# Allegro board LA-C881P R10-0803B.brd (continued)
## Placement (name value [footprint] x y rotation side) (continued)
PC311  0.1U_0402_25V6  [C_0402]  43.71 25.74 0 bottom
PC312  1U_0603_10V6K  [C_0603]  45.95 31.07 0 bottom
PC313  1U_0805_25V6K  [C_0805]  47.44 27.01 180 bottom
PC314  10U_0805_25V6K  [C_0805]  72.78 38.31 0 top
PC315  10U_0805_25V6K  [C_0805]  72.78 36.53 0 bottom
PC316  0.1U_0603_25V7K  [C_0603]  73.06 35.01 0 bottom
PC317  10U_0805_25V6K  [C_0805]  72.78 38.31 0 bottom
PC318  0.1U_0402_25V6  [C_0402]  40.36 24.27 90 bottom
PC319  0.1U_0603_25V7K  [C_0603]  71.86 43.07 90 top
PC320  0.1U_0603_25V7K  [C_0603]  73.06 35.01 0 top
PC321  10U_0805_25V6K  [C_0805]  72.78 36.53 0 top
PC322  0.047U_0603_25V7M  [C_0603]  47.35 28.53 180 bottom
PC323  0.1U_0603_25V7K  [C_0603]  73.89 31.33 270 top
PC324  10U_0805_25V6K  [C_0805]  68.58 31.49 270 bottom
PC325  10U_0805_25V6K  [C_0805]  72.28 31.5 270 bottom
PC326  10U_0805_25V6K  [C_0805]  70.48 31.5 270 bottom
PC327  10U_0805_25V6K  [C_0805]  68.6 31.47 270 top
PC328  10U_0805_25V6K  [C_0805]  70.5 31.45 270 top
PC329  10U_0805_25V6K  [C_0805]  72.29 31.45 270 top
PC330  100P_0402_50V8J  [C_0402]  39.47 25.18 270 bottom
PC331  100P_0402_50V8J  [C_0402]  39.47 25.18 270 top
PC332  100P_0402_50V8J  [C_0402]  39.27 28.91 0 top
PC333  1000P_0603_50V7K  [C_0603]  52.81 36.41 180 bottom
PC334  0.1U_0402_25V6  [C_0402]  44.3 34.13 270 bottom
PC335  0.1U_0402_25V6  [C_0402]  43.42 33.49 180 bottom
PC336  0.1U_0402_25V6  [C_0402]  42.51 34.38 0 bottom
PC337  1U_0603_25V6K  [C_0603]  40.49 33.11 90 bottom
PC400  100P_0402_50V8J  [C_0402]  162.92 64.3 270 bottom
PC401  0.01UF_0402_25V7K  [C_0402]  163.81 64.3 270 bottom
PC402  .1U_0402_16V7K  [C_0402]  173.41 58.63 180 bottom
PC403  1000P_0402_50V7K  [C_0402]  165.58 64.3 270 bottom
PC404  0.47U_0603_16V7K  [C_0603]  171.74 55.71 0 top
PC405  .1U_0402_16V7K  [C_0402]  175.36 58.38 270 top
PC406  0.1U_0402_25V6  [C_0402]  167.03 60.03 0 top
PC407  1U_0603_10V6K  [C_0603]  164.38 58.44 0 top
PC500  0.1U_0402_25V6  [C_0402]  89.76 22.44 270 top
PC501  2200P_0402_50V7K  [C_0402]  90.65 22.44 270 top
PC502  10U_0805_25V6K  [C_0805]  93.07 22.56 270 bottom
PC503  10U_0805_25V6K  [C_0805]  93.07 22.56 270 top
PC504  0.1U_0603_25V7K  [C_0603]  86.34 22.5 270 top
PC505  22U_0603_6.3V6M  [C_0603]  78.93 22.67 180 bottom
PC506  22U_0603_6.3V6M  [C_0603]  78.91 21.42 180 bottom
PC507  22U_0603_6.3V6M  [C_0603]  78.91 22.18 180 top
PC508  22U_0603_6.3V6M  [C_0603]  78.91 20.15 180 bottom
PC509  4.7U_0603_6.3V6M  [C_0603]  86.53 17.23 180 bottom
PC510  680P_0603_50V7K  [C_0603]  86.27 23.83 0 top
PC511  1000P_0402_25V8J  [C_0402]  90.15 17.94 270 bottom
PC512  0.1U_0603_25V7K  [C_0603]  59.98 44.03 180 top
PC513  0.1U_0402_25V6  [C_0402]  64.24 44.23 270 top
PC514  2200P_0402_50V7K  [C_0402]  63.35 44.23 270 top
PC515  10U_0805_25V6K  [C_0805]  66.78 44.37 270 bottom
PC516  10U_0805_25V6K  [C_0805]  68.56 44.37 270 bottom
PC517  4.7U_0603_6.3V6M  [C_0603]  61.25 38.31 180 top
PC518  22U_0603_6.3V6M  [C_0603]  55.92 49.11 180 bottom
PC519  22U_0603_6.3V6M  [C_0603]  55.95 46.63 180 bottom
PC520  22U_0603_6.3V6M  [C_0603]  55.92 47.84 180 bottom
PC521  22U_0603_6.3V6M  [C_0603]  53.91 46.63 180 top
PC522  22U_0603_6.3V6M  [C_0603]  53.89 49.11 180 top
PC523  4.7U_0603_6.3V6M  [C_0603]  61.25 37.93 180 bottom
PC524  680P_0603_50V7K  [C_0603]  60.74 39.84 0 top
PC525  1000P_0402_25V8J  [C_0402]  63.6 39.28 270 bottom
PC526  22U_0603_6.3V6M  [C_0603]  78.91 20.91 180 top
PC527  22U_0603_6.3V6M  [C_0603]  53.89 47.84 180 top
PC528  10U_0805_25V6K  [C_0805]  66.78 44.37 270 top
PC529  10U_0805_25V6K  [C_0805]  68.56 44.37 270 top
PC600  10U_0603_25V6M  [C_0603]  169.08 34.38 180 top
PC601  10U_0603_25V6M  [C_0603]  169.08 35.65 180 top
PC602  0.1U_0402_25V6  [C_0402]  168.96 36.79 180 top
PC603  2200P_0402_25V7K  [C_0402]  169.95 35.14 0 top
PC604  680P_0402_50V7K  [C_0402]  172.82 23.66 270 top
PC605  .1U_0402_16V7K  [C_0402]  172.95 27.97 270 top
PC606  1U_0402_6.3V6K  [C_0402]  172.49 28.91 0 top
PC607  2.2U_0402_6.3V6M  [C_0402]  172.49 29.8 0 top
PC608  22U_0603_6.3V6M  [C_0603]  166.09 26.95 270 top
PC609  330P_0402_50V7K  [C_0402]  173.41 30.69 180 top
PC610  22U_0603_6.3V6M  [C_0603]  164.78 23.29 90 top
PC611  22U_0603_6.3V6M  [C_0603]  164.82 19.96 270 top
PC612  22U_0603_6.3V6M  [C_0603]  167.36 19.96 270 top
PC613  22U_0603_6.3V6M  [C_0603]  166.09 19.96 270 top
PC614  1U_0402_10V6K  [C_0402]  166.55 31.96 180 top
PC615  22U_0603_6.3V6M  [C_0603]  166.66 29.55 180 top
PC616  22U_0603_6.3V6M  [C_0603]  166.66 30.82 180 top
PC617  0.1U_0402_10V7K  [C_0402]  164.95 32.98 90 top
PC618  0.1U_0402_10V7K  [C_0402]  163.93 29.42 180 top
PC700  0.22U_0402_10V6K  [C_0402]  203.1 61.43 0 bottom
PC701  680P_0402_50V7K  [C_0402]  201.88 57.57 270 bottom
PC702  2200P_0402_50V7K  [C_0402]  195.3 63.03 270 top
PC703  0.1U_0603_25V7K  [C_0603]  199.49 61.49 270 top
PC704  0.1U_0402_25V6  [C_0402]  195.3 63.03 270 bottom
PC705  10U_0805_25V6K  [C_0805]  196.7 63.8 270 top
PC706  10U_0805_25V6K  [C_0805]  196.7 63.8 270 bottom
PC707  22P_0402_50V8J  [C_0402]  204.01 64.09 180 bottom
PC708  22U_0805_6.3VAM  [C_0805]  194.79 55.67 270 top
PC709  22U_0805_6.3VAM  [C_0805]  194.79 57.4 90 top
PC710  22U_0805_6.3VAM  [C_0805]  194.77 55.67 270 bottom
PC711  22U_0805_6.3VAM  [C_0805]  194.74 57.4 90 bottom
PC712  4.7U_0603_6.3V6K  [C_0603]  202.92 65.68 90 bottom
PC713  4.7U_0603_6.3V6K  [C_0603]  200.44 66.25 0 bottom
PC800  0.1U_0402_25V6  [C_0402]  173.97 78.06 90 top
PC801  22P_0402_50V8J  [C_0402]  170.66 70.82 90 top
PC802  22U_0805_6.3VAM  [C_0805]  168.12 73.36 0 top
PC803  0.1U_0402_25V6  [C_0402]  176.63 76.16 0 top
PC804  2200P_0402_50V7K  [C_0402]  176.63 75.27 0 top
PC805  10U_0805_25V6K  [C_0805]  176.76 77.56 0 top
PC806  3300P_0402_50V7-K  [C_0402]  176.63 74.25 0 top
PC807  680P_0402_50V7K  [C_0402]  170.54 79.84 180 top
PC900  0.1U_0402_25V6  [C_0402]  171.43 43.39 90 top
PC901  22P_0402_50V8J  [C_0402]  166.73 38.19 90 top
PC902  22U_0805_6.3VAM  [C_0805]  161.99 44.03 180 top
PC903  0.1U_0402_25V6  [C_0402]  171.43 41.61 90 top
PC904  2200P_0402_50V7K  [C_0402]  172.31 41.61 90 top
PC905  10U_0805_25V6K  [C_0805]  171.81 40.47 270 top
PC906  3300P_0402_50V7-K  [C_0402]  170.28 38.9 270 top
PC907  680P_0402_50V7K  [C_0402]  163.6 40.45 270 top
PC1004  0.1U_0402_25V6  [C_0402]  64.49 51.9 270 bottom
PC1005  0.22U_0603_25V7K  [C_0603]  64.62 55.71 90 bottom
PC1006  47P_0402_50V8J~D  [C_0402]  62.33 51.01 180 top
PC1007  1U_0603_10V6K  [C_0603]  65.51 53.3 0 bottom
PC1014  220P_0402_50V7K  [C_0402]  69.7 46.82 270 top
PC1019  0.01U_0402_50V7K  [C_0402]  67.79 46.44 90 bottom
PC1020  2200P_0402_50V7K  [C_0402]  65.89 46.06 90 top
PC1021  68P_0402_50V8J  [C_0402]  66.9 48.09 90 top
PC1022  0.082U_0402_16V7K  [C_0402]  68.68 48.22 180 bottom
PC1056  68P_0402_50V8J  [C_0402]  70.97 53.17 0 bottom
PC1064  2200P_0402_50V7K  [C_0402]  71.48 55.84 270 bottom
PC1065  330P_0402_50V7K  [C_0402]  70.97 52.28 0 bottom
PC1066  10U_0805_25V6K  [C_0805]  66.65 62.16 90 top
PC1067  0.033U_0402_16V7K  [C_0402]  73.64 56.9 0 bottom
PC1068  2200P_0402_25V7K  [C_0402]  67.54 58.17 90 top
PC1069  2200P_0402_50V7K  [C_0402]  73.89 56.73 90 top
PC1070  0.022U_0402_16V7K  [C_0402]  70.59 48.22 90 top
PC1071  0.047U_0402_25V7K  [C_0402]  67.54 58.17 90 bottom
PC1072  2200P_0402_25V7K  [C_0402]  69.52 59.39 180 top
PC1073  100U_D_20VM_R55M  [C_D]  77.19 43.01 0 bottom
PC1074  0.01U_0402_50V7K  [C_0402]  70.59 58.25 0 bottom
PC1075  0.047U_0402_25V7K  [C_0402]  73.64 56.02 0 bottom
PC1076  2200P_0402_50V7K  [C_0402]  69.06 62.49 90 top
PC1077  0.082U_0402_16V7K  [C_0402]  69.57 58.25 180 bottom
PC1078  0.1U_0402_25V6  [C_0402]  66.65 58.17 90 bottom
PC1079  0.1U_0402_25V6K~D  [C_0402]  68.17 62.49 90 top
PC1080  330P_0402_50V7K  [C_0402]  69.57 56.22 270 bottom
PC1081  10P_0402_50V8J  [C_0402]  68.68 56.22 270 bottom
PC1082  0.22U_0603_16V7K  [C_0603]  61.57 61.87 270 top
PC1083  .1U_0402_16V7K  [C_0402]  75.54 56.85 270 bottom
PC1084  .1U_0402_16V7K  [C_0402]  72.37 48.22 90 top
PC1085  0.033U_0402_16V7K  [C_0402]  69.7 48.22 0 bottom
PC1086  680P_0603_50V7K  [C_0603]  69.32 67.27 180 bottom
PC1087  .1U_0402_16V7K  [C_0402]  66.65 60.03 0 bottom
PC1088  2200P_0402_50V7K  [C_0402]  72.37 50 180 bottom
PC1089  2200P_0402_25V7K  [C_0402]  66.9 55.33 0 bottom
PC1090  1500P_0402_50V7K  [C_0402]  74.91 54.06 0 top
PC1091  330P_0402_50V7K  [C_0402]  68.61 59.39 0 bottom
PC1092  0.082U_0402_16V7K  [C_0402]  73.89 54.95 90 top
PC1093  10U_0805_25V6K  [C_0805]  66.65 62.44 90 bottom
PC1094  0.1U_0402_25V6  [C_0402]  69.7 49.11 0 bottom
PC1095  680P_0402_50V7K  [C_0402]  66.9 46.95 270 top
PC1096  680P_0402_50V7K  [C_0402]  77.06 51.39 180 top
PC1097  1U_0402_10V6K  [C_0402]  64.16 65.24 0 top
PC1098  330P_0402_50V7K  [C_0402]  68.68 46.44 90 bottom
PC1099  0.01U_0402_50V7K  [C_0402]  75.79 55.84 180 top
PC1100  10U_0805_25V6K  [C_0805]  80.79 58.89 0 top
PC1101  10U_0805_25V6K  [C_0805]  80.79 60.66 0 bottom
PC1102  10U_0805_25V6K  [C_0805]  80.79 60.66 0 top
PC1103  0.1U_0402_25V6K~D  [C_0402]  78.92 59.65 180 top
PC1104  2200P_0402_50V7K  [C_0402]  80.42 62.06 0 top
PC1105  10U_0805_25V6K  [C_0805]  80.79 58.89 0 bottom
PC1106  0.22U_0603_16V7K  [C_0603]  84.62 67.9 180 top
PC1107  10U_0805_25V6K  [C_0805]  80.49 52.16 0 bottom
PC1108  10U_0805_25V6K  [C_0805]  80.49 52.16 0 top
PC1109  10U_0805_25V6K  [C_0805]  78.97 53.64 270 bottom
PC1110  1000P_0402_50V7K  [C_0402]  80.42 63.84 0 top
PC1111  2200P_0402_50V7K  [C_0402]  80.42 54.44 0 top
PC1112  0.1U_0402_25V6K~D  [C_0402]  80.42 53.55 0 top
PC1113  10P_0402_50V8J  [C_0402]  80.42 62.95 0 top
PC1114  1U_0402_10V6K  [C_0402]  84.94 67.01 90 bottom
PC1115  47P_0603_50V8J  [C_0603]  85.38 61.05 180 top
PC1116  0.22U_0603_16V7K  [C_0603]  77.64 57.62 0 top
PC1117  10P_0402_50V8J  [C_0402]  80.42 56.22 0 top
PC1118  1000P_0402_50V7K  [C_0402]  80.42 55.33 0 top
PC1119  1U_0402_10V6K  [C_0402]  85.5 58.38 0 bottom
PC1120  10U_0805_25V6K  [C_0805]  78.97 40.73 0 top
PC1121  10U_0805_25V6K  [C_0805]  78.97 44.28 0 top
PC1122  10U_0805_25V6K  [C_0805]  78.97 42.5 0 top
PC1123  0.1U_0402_25V6K~D  [C_0402]  80.29 45.68 0 top
PC1124  2200P_0402_50V7K  [C_0402]  80.29 46.57 0 top
PC1125  47P_0603_50V8J  [C_0603]  85.26 53.68 180 top
PC1126  0.22U_0603_16V7K  [C_0603]  77.38 50.12 0 top
PC1127  10P_0402_50V8J  [C_0402]  80.29 47.46 0 top
PC1128  1000P_0402_50V7K  [C_0402]  80.29 48.35 0 top
PC1129  1U_0402_10V6K  [C_0402]  85.5 50.76 0 bottom
PC1130  47P_0603_50V8J  [C_0603]  85.51 46.06 180 top
PC1131  330P_0402_50V8J  [C_0402]  67.67 51.65 270 bottom
PC1132  330P_0402_50V7K  [C_0402]  75.79 54.95 180 top
PC1133  0.022U_0402_16V7K  [C_0402]  71.48 48.22 90 top
PC1134  680P_0402_50V7K  [C_0402]  71.55 60.03 180 top
PC1135  100U_D_20VM_R55M  [C_D]  77.19 38.31 0 bottom
PC1200  22U_0603_6.3V6M  [C_0603]  128.94 62.06 0 top
PC1201  22U_0603_6.3V6M  [C_0603]  132.88 62.06 180 top
PC1202  22U_0603_6.3V6M  [C_0603]  129.01 59.46 90 top
PC1203  22U_0603_6.3V6M  [C_0603]  130.28 59.46 90 top
PC1204  22U_0603_6.3V6M  [C_0603]  131.55 59.46 90 top
PC1205  22U_0603_6.3V6M  [C_0603]  132.82 59.46 90 top
PC1206  22U_0603_6.3V6M  [C_0603]  132.94 65.17 270 top
PC1207  22U_0603_6.3V6M  [C_0603]  131.67 65.17 270 top
PC1208  22U_0603_6.3V6M  [C_0603]  130.4 65.17 270 top
PC1209  22U_0603_6.3V6M  [C_0603]  129.13 65.17 270 top
PC1210  22U_0603_6.3V6M  [C_0603]  99.52 71.7 90 top
PC1211  22U_0603_6.3V6M  [C_0603]  99.67 66.13 270 top
PC1212  22U_0603_6.3V6M  [C_0603]  94.59 71.71 90 top
PC1213  22U_0603_6.3V6M  [C_0603]  96.94 61.81 0 bottom
PC1214  22U_0603_6.3V6M  [C_0603]  96.94 61.81 0 top
PC1215  22U_0603_6.3V6M  [C_0603]  96.94 63.08 0 top
PC1216  22U_0603_6.3V6M  [C_0603]  95.86 71.71 90 top
PC1217  22U_0603_6.3V6M  [C_0603]  109.83 64.66 90 top
PC1218  22U_0603_6.3V6M  [C_0603]  106.27 61.81 90 top
PC1219  22U_0603_6.3V6M  [C_0603]  126.21 58.12 90 top
PC1220  22U_0603_6.3V6M  [C_0603]  123.67 58.12 90 top
PC1221  22U_0603_6.3V6M  [C_0603]  126.09 65.24 270 top
PC1222  22U_0603_6.3V6M  [C_0603]  124.82 65.24 270 top
PC1223  22U_0603_6.3V6M  [C_0603]  123.55 65.24 270 top
PC1224  22U_0603_6.3V6M  [C_0603]  108.56 64.6 90 top
PC1225  22U_0603_6.3V6M  [C_0603]  111.35 61.81 90 top
PC1226  22U_0603_6.3V6M  [C_0603]  113.26 60.41 270 top
PC1227  22U_0603_6.3V6M  [C_0603]  115.29 64.6 90 top
PC1228  22U_0603_6.3V6M  [C_0603]  110.08 61.81 90 top
PC1229  22U_0603_6.3V6M  [C_0603]  115.29 61.81 90 top
PC1230  22U_0603_6.3V6M  [C_0603]  98.3 71.71 90 top
PC1231  22U_0603_6.3V6M  [C_0603]  96.94 63.08 0 bottom
PC1232  22U_0603_6.3V6M  [C_0603]  107.16 69.49 270 top
PC1233  22U_0603_6.3V6M  [C_0603]  97.08 71.71 90 top
PC1234  22U_0603_6.3V6M  [C_0603]  102.64 69.49 270 bottom
PC1235  22U_0603_6.3V6M  [C_0603]  100.94 66.13 270 top
PC1236  22U_0603_6.3V6M  [C_0603]  98.27 66.13 270 top
PC1237  22U_0603_6.3V6M  [C_0603]  129.9 75.78 180 bottom
PC1238  22U_0603_6.3V6M  [C_0603]  98.4 71.73 90 bottom
PC1239  22U_0603_6.3V6M  [C_0603]  97.13 71.73 90 bottom
PC1240  22U_0603_6.3V6M  [C_0603]  96.88 66.13 270 top
PC1241  22U_0603_6.3V6M  [C_0603]  95.86 71.73 90 bottom
PC1242  22U_0603_6.3V6M  [C_0603]  102.64 69.49 270 top
PC1243  22U_0603_6.3V6M  [C_0603]  104.24 69.49 270 top
PC1244  22U_0603_6.3V6M  [C_0603]  105.89 69.49 270 top
PC1245  22U_0603_6.3V6M  [C_0603]  101.07 69.43 270 top
PC1246  22U_0603_6.3V6M  [C_0603]  107.29 64.54 90 top
PC1247  22U_0603_6.3V6M  [C_0603]  106.02 64.54 90 top
PC1248  22U_0603_6.3V6M  [C_0603]  105.39 58.98 90 top
PC1249  22U_0603_6.3V6M  [C_0603]  99.67 60.28 270 top
PC1250  22U_0603_6.3V6M  [C_0603]  102.21 64.54 90 top
PC1251  22U_0603_6.3V6M  [C_0603]  103.48 64.54 90 top
PC1252  22U_0603_6.3V6M  [C_0603]  104.75 64.54 90 top
PC1253  22U_0603_6.3V6M  [C_0603]  103.99 58.89 90 top
PC1254  22U_0603_6.3V6M  [C_0603]  102.46 58.89 90 top
PC1255  22U_0603_6.3V6M  [C_0603]  101.07 58.89 90 top
PC1256  22U_0603_6.3V6M  [C_0603]  101.07 61.81 90 top
PC1257  22U_0603_6.3V6M  [C_0603]  105 61.81 90 top
PC1258  22U_0603_6.3V6M  [C_0603]  107.54 61.81 90 top
PC1259  1U_0201_6.3V6M  [C_0201]  134.58 66.02 0 top
PC1260  1U_0201_6.3V6M  [C_0201]  127.74 63.46 180 top
PC1261  1U_0201_6.3V6M  [C_0201]  127.74 60.92 180 top
PC1262  1U_0201_6.3V6M  [C_0201]  134.47 60.28 0 top
PC1263  1U_0201_6.3V6M  [C_0201]  134.47 65.36 0 top
PC1264  1U_0201_6.3V6M  [C_0201]  134.47 61.55 0 top
PC1265  1U_0201_6.3V6M  [C_0201]  134.47 62.82 0 top
PC1266  1U_0201_6.3V6M  [C_0201]  127.74 59.65 180 top
PC1267  1U_0201_6.3V6M  [C_0201]  127.74 62.82 180 top
PC1268  1U_0201_6.3V6M  [C_0201]  127.74 64.73 180 top
PC1269  1U_0201_6.3V6M  [C_0201]  127.74 65.36 180 top
PC1270  1U_0201_6.3V6M  [C_0201]  99.54 68.28 0 top
PC1271  1U_0201_6.3V6M  [C_0201]  99.54 67.65 0 top
PC1272  1U_0201_6.3V6M  [C_0201]  127.74 66 180 top
PC1273  1U_0201_6.3V6M  [C_0201]  99.54 68.92 0 top
PC1274  1U_0201_6.3V6M  [C_0201]  94.84 71.84 90 bottom
PC1275  1U_0201_6.3V6M  [C_0201]  128.75 67.78 0 top
PC1276  1U_0201_6.3V6M  [C_0201]  126.21 66.63 0 top
PC1277  1U_0201_6.3V6M  [C_0201]  118.09 65.87 90 top
PC1278  1U_0201_6.3V6M  [C_0201]  120.37 56.85 270 top
PC1279  1U_0201_6.3V6M  [C_0201]  122.53 56.85 270 top
PC1280  1U_0201_6.3V6M  [C_0201]  123.8 56.85 270 top
PC1281  1U_0201_6.3V6M  [C_0201]  126.21 56.85 270 top
PC1282  1U_0201_6.3V6M  [C_0201]  119.1 56.85 270 top
PC1283  1U_0201_6.3V6M  [C_0201]  125.07 56.85 270 top
PC1284  1U_0201_6.3V6M  [C_0201]  126.59 67.52 90 top
PC1285  1U_0201_6.3V6M  [C_0201]  127.36 56.77 270 top
PC1286  1U_0201_6.3V6M  [C_0201]  124.51 66.51 180 top
PC1287  1U_0201_6.3V6M  [C_0201]  119.36 66 90 top
PC1288  1U_0201_6.3V6M  [C_0201]  127.74 61.55 180 top
PC1289  1U_0201_6.3V6M  [C_0201]  94.21 71.84 90 bottom
PC1290  1U_0201_6.3V6M  [C_0201]  99.54 67.01 0 top
PC1291  1U_0201_6.3V6M  [C_0201]  132.36 56.73 0 top
PC1292  1U_0201_6.3V6M  [C_0201]  131.69 56.17 180 top
PC1293  1U_0201_6.3V6M  [C_0201]  127.74 59.01 180 top
PC1294  1U_0201_6.3V6M  [C_0201]  134.47 60.92 0 top
PC1295  1U_0201_6.3V6M  [C_0201]  134.47 62.19 0 top
PC1296  1U_0201_6.3V6M  [C_0201]  134.47 64.73 0 top
PC1297  1U_0201_6.3V6M  [C_0201]  127.74 60.28 180 top
PC1298  1U_0201_6.3V6M  [C_0201]  127.74 62.19 180 top
PC1299  1U_0201_6.3V6M  [C_0201]  127.74 64.09 180 top
PC1300  1U_0201_6.3V6M  [C_0201]  128.07 67.78 180 top
PC1301  1U_0201_6.3V6M  [C_0201]  133.71 55.58 90 top
PC1302  1U_0201_6.3V6M  [C_0201]  134.47 63.46 0 top
PC1303  1U_0201_6.3V6M  [C_0201]  131.67 56.73 180 top
PC1304  1U_0201_6.3V6M  [C_0201]  134.47 64.09 0 top
PC1305  1U_0201_6.3V6M  [C_0201]  132.35 56.17 0 top
PC1306  330_B2_2.5VM_R9M  [C_B2]  97.51 44.89 90 bottom
PC1307  330_B2_2.5VM_R9M  [C_B2]  97.03 47.96 180 bottom
PC1308  330_B2_2.5VM_R9M  [C_B2]  97.03 68.54 180 bottom
PC1309  330_B2_2.5VM_R9M  [C_B2]  97.02 65.33 180 bottom
PC1310  22U_0603_6.3V6M  [C_0603]  135.48 77.17 90 top
PC1311  22U_0603_6.3V6M  [C_0603]  136.25 71.71 0 top
PC1312  22U_0603_6.3V6M  [C_0603]  76.68 67.01 180 bottom
PC1313  22U_0603_6.3V6M  [C_0603]  139.29 77.17 90 top
PC1314  22U_0603_6.3V6M  [C_0603]  135.67 73.36 90 top
PC1315  22U_0603_6.3V6M  [C_0603]  137.14 68.79 90 top
PC1316  22U_0603_6.3V6M  [C_0603]  138.79 64.86 0 top
PC1317  22U_0603_6.3V6M  [C_0603]  138.02 59.9 0 top
PC1318  22U_0603_6.3V6M  [C_0603]  137.64 63.71 180 top
PC1319  22U_0603_6.3V6M  [C_0603]  137.64 66.25 180 top
PC1320  22U_0603_6.3V6M  [C_0603]  137.64 64.98 180 top
PC1321  22U_0603_6.3V6M  [C_0603]  76.68 68.28 180 bottom
PC1322  1U_0201_6.3V6M  [C_0201]  138.28 58.63 180 top
PC1323  1U_0201_6.3V6M  [C_0201]  138.88 58.63 0 top
PC1324  1U_0201_6.3V6M  [C_0201]  138.66 67.9 0 top
PC1325  1U_0201_6.3V6M  [C_0201]  137.64 67.9 180 top
PC1326  1U_0201_6.3V6M  [C_0201]  136.41 67.78 180 top
PC1327  1U_0201_6.3V6M  [C_0201]  135.79 68.73 90 top
PC1328  1U_0201_6.3V6M  [C_0201]  134.85 66.63 0 top
PC1329  330_B2_2.5VM_R9M  [C_B2]  97.64 56.58 90 bottom
PC1330  22U_0603_6.3V6M  [C_0603]  124.82 61.17 90 top
PC1331  22U_0603_6.3V6M  [C_0603]  102.46 61.81 90 top
PC1332  22U_0603_6.3V6M  [C_0603]  103.73 61.81 90 top
PC1333  22U_0603_6.3V6M  [C_0603]  119.86 58.12 90 top
PC1334  22U_0603_6.3V6M  [C_0603]  108.81 61.81 90 top
PC1335  22U_0603_6.3V6M  [C_0603]  106.66 58.98 90 top
PC1336  22U_0603_6.3V6M  [C_0603]  124.94 58.12 90 top
PC1337  22U_0603_6.3V6M  [C_0603]  122.4 58.12 90 top
PC1338  1U_0201_6.3V6M  [C_0201]  119.22 67.83 180 top
PC1339  1U_0201_6.3V6M  [C_0201]  121.13 67.52 90 top
PC1340  1U_0201_6.3V6M  [C_0201]  123.93 67.52 90 top
PC1341  1U_0201_6.3V6M  [C_0201]  125.71 67.52 90 top
PC1342  1U_0201_6.3V6M  [C_0201]  117.2 66.72 90 top
PC1343  1U_0201_6.3V6M  [C_0201]  118.72 65.87 90 top
PC1344  10U_0603_6.3V6M  [C_0603]  121.13 58.12 90 top
PC1345  10U_0603_6.3V6M  [C_0603]  126.09 61.17 90 top
PC1346  10U_0603_6.3V6M  [C_0603]  123.55 61.17 90 top
PC1347  10U_0603_6.3V6M  [C_0603]  122.28 65.11 270 top
PC1348  10U_0603_6.3V6M  [C_0603]  121.01 65.11 270 top
PC1349  10U_0603_6.3V6M  [C_0603]  119.74 65.11 270 top
PC1350  10U_0603_6.3V6M  [C_0603]  111.6 60.36 270 top
PC1351  10U_0603_6.3V6M  [C_0603]  115.04 60.54 270 top
PC1352  10U_0603_6.3V6M  [C_0603]  111.1 64.66 90 top
PC1353  10U_0603_6.3V6M  [C_0603]  112.88 64.6 90 top
PC1354  10U_0603_6.3V6M  [C_0603]  113.26 61.81 90 top
PC1355  330_B2_2.5VM_R9M  [C_B2]  95.76 51.27 180 bottom
PC1400  0.1U_0402_25V6  [C_0402]  174.73 53.48 90 top
PC1401  10U_0603_25V6M  [C_0603]  177.78 51.52 0 bottom
PC1402  10U_0603_25V6M  [C_0603]  177.78 50.78 0 top
PC1403  22U_0603_6.3V6M  [C_0603]  169.58 52.16 0 top
PC1404  22U_0603_6.3V6M  [C_0603]  167.87 50.89 180 top
PC1405  22U_0603_6.3V6M  [C_0603]  168.63 52.16 180 top
PC1406  22U_0603_6.3V6M  [C_0603]  193.97 72.09 180 top
PC1408  0.1U_0402_25V6  [C_0402]  177.65 49.64 0 top
PC1409  2200P_0402_50V7K  [C_0402]  177.65 50.38 0 bottom
PC1410  680P_0402_50V7K  [C_0402]  168 48.22 90 top
PC1411  470P_0402_50V7K  [C_0402]  174.85 46.69 270 top
PC1412  0.1U_0402_25V6  [C_0402]  200.89 76.62 270 bottom
PC1413  10U_0603_25V6M  [C_0603]  202.98 76.92 0 top
PC1414  10U_0603_25V6M  [C_0603]  202.98 78.13 0 top
PC1415  22U_0603_6.3V6M  [C_0603]  193.97 73.36 180 top
PC1416  22U_0603_6.3V6M  [C_0603]  193.97 74.63 180 top
PC1417  0.1U_0402_25V6  [C_0402]  202.97 74.81 0 top
PC1418  2200P_0402_50V7K  [C_0402]  202.97 75.78 0 top
PC1419  680P_0402_50V7K  [C_0402]  196.44 70.82 180 top
PC1420  470P_0402_50V7K  [C_0402]  200.25 72.78 90 bottom
PC1500  0.1U_0402_25V6  [C_0402]  88.57 41.87 180 top
PC1501  10U_0603_25V6M  [C_0603]  86.26 40.79 90 bottom
PC1502  10U_0603_25V6M  [C_0603]  86.26 40.79 90 top
PC1503  22U_0603_6.3V6M  [C_0603]  94.08 42 90 bottom
PC1504  22U_0603_6.3V6M  [C_0603]  92.81 42 90 bottom
PC1505  22U_0603_6.3V6M  [C_0603]  94.08 41.8 90 top
PC1506  22U_0603_6.3V6M  [C_0603]  89.26 31.96 90 top
PC1508  0.1U_0402_25V6  [C_0402]  87.17 39.44 0 top
PC1509  2200P_0402_50V7K  [C_0402]  87.17 38.53 0 top
PC1510  680P_0402_50V7K  [C_0402]  94.72 37.17 0 bottom
PC1511  470P_0402_50V7K  [C_0402]  87.73 35.85 270 top
PC1512  0.1U_0402_25V6  [C_0402]  84.29 33.02 180 top
PC1513  10U_0603_25V6M  [C_0603]  82.02 30.37 90 top
PC1514  10U_0603_25V6M  [C_0603]  82.02 30.37 90 bottom
PC1515  22U_0603_6.3V6M  [C_0603]  89.26 31.93 90 bottom
PC1516  22U_0603_6.3V6M  [C_0603]  90.5 31.94 90 bottom
PC1517  0.1U_0402_25V6  [C_0402]  83.16 30.62 90 top
PC1518  2200P_0402_50V7K  [C_0402]  83.16 30.62 90 bottom
PC1519  680P_0402_50V7K  [C_0402]  91.03 25.87 90 bottom
PC1520  470P_0402_50V7K  [C_0402]  84.56 26.45 270 bottom
PD100  -  [TVNST52302AB0_SOT523-3]  66.78 20.53 180 top
PD101  -  [TVNST52302AB0_SOT523-3]  68.81 21.93 0 top
PD102  AZ5125-01H.R7G_SOD523-2  [AZ5125-01HPR7G_SOD523-2]  26.94 72.25 90 top
PD200  BAT54CW-7-F_SOT323-3~D  [BAT54CW_SOT323-3]  57.5 58.76 90 top
PD201  -  [SDMK0340L-7-F_SOD323-2]  90.33 77.05 180 top
PD202  -  [SDMK0340L-7-F_SOD323-2]  58.55 53.38 270 top
PD203  -  [SDMK0340L-7-F_SOD323-2]  89.69 70.32 180 top
PD204  -  [SDMK0340L-7-F_SOD323-2]  57.81 69.9 270 top
PD205  -  [SDMK0340L-7-F_SOD323-2]  59.59 69.97 270 top
PD206  -  [SDMK0340L-7-F_SOD323-2]  96.97 74.7 0 top
PD300  -  [SDMK0340L-7-F_SOD323-2]  42.14 22.56 270 top
PD301  -  [SDMK0340L-7-F_SOD323-2]  37.69 19.77 270 top
PD302  -  [SDMK0340L-7-F_SOD323-2]  39.47 19.77 270 top
PH1005  10K_0402_5%_B25/50 4250K  [R_0402]  90.15 43.39 0 bottom
PH1006  10K_0402_5%_B25/50 4250K  [R_0402]  73.84 59.01 0 bottom
PH1007  470K_0402_5%_ TSM0B474J4702RE  [R_0402]  82.19 50.76 0 bottom
PH1008  470K_0402_5%_ TSM0B474J4702RE  [R_0402]  83.85 60.92 0 bottom
PH1009  10K_0402_5%_B25/50 4250K  [R_0402]  89.81 67.14 0 bottom
PJP14  PAD-OPEN1X1M  [JUMP_43X39]  28.68 19.77 270 bottom
PJP15  PAD-OPEN1X1M  [JUMP_43X39]  170.36 63.13 180 top
PJP300  -  [JUMP_43X39]  41.76 30.74 90 top
PJP500  -  [JUMP_43X118]  76.18 17.91 270 bottom
PJP501  -  [JUMP_43X118]  59.03 46.78 90 bottom
PJP600  -  [JUMP_43X118]  162.83 21.04 180 top
PJP601  -  [JUMP_43X39]  164.64 27.77 180 top
PJP700  -  [JUMP_43X79]  192.55 56.09 180 bottom
PJP800  -  [JUMP_43X39]  168.12 71.54 270 top
PJP900  -  [JUMP_43X39]  161.85 42 180 top
PJP1002  PAD-OPEN 4X4M  [JUMP_43X118]  73.68 41.87 180 bottom
PJP1400  -  [JUMP_43X79]  169.27 53.89 90 top
PJP1401  -  [JUMP_43X79]  193.4 69.55 180 top
PL100  HCB2012KF-121T50_0805  [TAI-T_HCB2012KF-121T50_2P]  76.07 24.28 180 bottom
PL101  HCB2012KF-121T50_0805  [TAI-T_HCB2012KF-121T50_2P]  76.06 25.96 180 bottom
PL102  BLM15AG102SN1D_2P  [MURAT_BLM15AG102SN1D_2P]  28.04 73.28 270 top
PL103  HCB2012KF-121T50_0805  [TAI-T_HCB2012KF-121T50_2P]  28.55 78.19 0 bottom
PL104  HCB2012KF-121T50_0805  [TAI-T_HCB2012KF-121T50_2P]  25.38 73.11 90 top
PL300  HCB2012KF-121T50_0805  [TAI-T_HCB2012KF-121T50_2P]  49.36 31.64 90 bottom
PL301  3.3UH_6.3A_20%_7X7X3_M  [L_7X7X3_M_2P]  59.58 32.6 0 bottom
PL500  HCB2012KF-121T50_0805  [TAI-T_HCB2012KF-121T50_2P]  93.07 25.87 270 bottom
PL501  1.5UH_TMPC0518HP-1R5MG-D_6A_20%  [TAI-T_TMPC0518HP-1R5MG-D_2P]  85.57 20.66 180 bottom
PL504  1.5UH_PCMC063T-1R5MN_9A_20%  [CYNTE_PCMC063T-1R5MN_2P]  59.28 42 180 bottom
PL600  HCB2012KF-121T50_0805  [TAI-T_HCB2012KF-121T50_2P]  172.3 36.41 180 top
PL601  TMPC0512HP-1R0MG-D_5A_20%  [CYNTE_PCMB051B-1R0MS_2P]  169.52 26.63 270 top
PL700  HCB2012KF-121T50_0805  [TAI-T_HCB2012KF-121T50_2P]  196.7 67.18 270 bottom
PL701  1UH_6.6A_20%_5X5X3_M  [L_5X5X3_M_2P]  198.53 59.54 270 bottom
PL800  HCB1608KF-121T30_0603  [TAI-T_HCB1608KF-121T3_L0603_2P]  177.65 79.21 180 top
PL801  2.2UH_1239AS-H-2R2N-P2_1.3A_30%  [TOKO_1239AS-H-2R2N-P2_2P]  170.03 75.52 180 top
PL900  HCB1608KF-121T30_0603  [TAI-T_HCB1608KF-121T3_L0603_2P]  173.27 38.78 90 top
PL901  2.2UH_1239AS-H-2R2N-P2_1.3A_30%  [TOKO_1239AS-H-2R2N-P2_2P]  165.33 44.03 180 top
PL1004  HCB2012KF-121T50_0805  [TAI-T_HCB2012KF-121T50_2P]  64.75 61.78 180 bottom
PL1005  1UH_6.6A_20%_5X5X3_M  [L_5X5X3_M_2P]  72.98 62.38 0 bottom
PL1100  0.15UH_MMD06CZER15MG_37A_20%  [NEC_MPC0740LR42C_2P]  87.28 63.04 0 bottom
PL1101  0.15UH_MMD06CZER15MG_37A_20%  [NEC_MPC0740LR42C_2P]  87.3 54.95 0 bottom
PL1102  0.15UH_MMD06CZER15MG_37A_20%  [NEC_MPC0740LR42C_2P]  87.29 47.46 0 bottom
PL1400  HCB1608KF-121T30_0603  [TAI-T_HCB1608KF-121T3_L0603_2P]  179.55 52.05 180 top
PL1401  1UH_1277AS-H-1R0N-P2_3.3A_30%  [TOKO_1277AS-H-1R0N-P2_2P]  169.9 48.47 90 top
PL1402  HCB1608KF-121T30_0603  [TAI-T_HCB1608KF-121T3_L0603_2P]  204.1 79.46 180 top
PL1403  1UH_1277AS-H-1R0N-P2_3.3A_30%  [TOKO_1277AS-H-1R0N-P2_2P]  196.06 73.24 90 top
PL1500  HCB1608KF-121T30_0603  [TAI-T_HCB1608KF-121T3_L0603_2P]  86.21 37.64 90 bottom
PL1501  1UH_1277AS-H-1R0N-P2_3.3A_30%  [TOKO_1277AS-H-1R0N-P2_2P]  93.19 38.44 90 bottom
PL1502  HCB1608KF-121T30_0603  [TAI-T_HCB1608KF-121T3_L0603_2P]  80.75 31.75 270 bottom
PL1503  1UH_1277AS-H-1R0N-P2_3.3A_30%  [TOKO_1277AS-H-1R0N-P2_2P]  90.02 28.41 90 bottom
PQ100  FDV301N_G_NL_SOT23-3  [FDV301N_NL_SOT23-3]  30.23 68.54 90 top
PQ101  MMST3904-7-F_SOT323  [MMST3904-7-F_SOT323-3]  31.47 70.89 0 top
PQ200  AON2409_DFN6-8  [AON2405_DFN6-8]  56 51.55 180 bottom
PQ201  AON2409_DFN6-8  [AON2405_DFN6-8]  56.21 56.36 270 bottom
PQ202  AON2409_DFN6-8  [AON2405_DFN6-8]  33.14 75.17 180 bottom
PQ203  AON2409_DFN6-8  [AON2405_DFN6-8]  34.42 75.25 90 bottom
PQ204  LP2305LT1G_SOT23-3  [NTR4502PT1G_SOT23-3]  55.73 50.86 0 top
PQ205  LP2305LT1G_SOT23-3  [NTR4502PT1G_SOT23-3]  18.77 76.82 180 top
PQ206  -  [DMN66D0LDW-7_SOT363-6]  56.12 57.58 180 top
PQ207  -  [DMN66D0LDW-7_SOT363-6]  34.66 74.44 180 top
PQ208  -  [DMN66D0LDW-7_SOT363-6]  62.96 47.57 90 top
PQ209  -  [DMN66D0LDW-7_SOT363-6]  21.07 72.92 180 top
PQ210  AON2409_DFN6-8  [AON2405_DFN6-8]  46.61 74.49 90 bottom
PQ211  AON2409_DFN6-8  [AON2405_DFN6-8]  46.82 78.67 0 bottom
PQ212  AON2409_DFN6-8  [AON2405_DFN6-8]  45.57 76.92 180 bottom
PQ213  LP2305LT1G_SOT23-3  [NTR4502PT1G_SOT23-3]  55.35 60.64 0 top
PQ214  LP2305LT1G_SOT23-3  [NTR4502PT1G_SOT23-3]  46.58 72.12 180 top
PQ215  -  [DMN66D0LDW-7_SOT363-6]  59.43 64.41 180 top
PQ216  -  [DMN66D0LDW-7_SOT363-6]  51.98 68.05 270 top
PQ217  -  [DMN66D0LDW-7_SOT363-6]  53.76 70.17 90 top
PQ218  -  [DMN66D0LDW-7_SOT363-6]  88.43 68.55 270 top
PQ219  -  [DMN66D0LDW-7_SOT363-6]  62.44 19.84 0 top
PQ220  S TR 2N7002KW 1N SOT323-3  [SSM3K7002FU_SC70-3]  58.72 20.53 270 top
PQ221  LP2305LT1G_SOT23-3  [NTR4502PT1G_SOT23-3]  56.24 40.47 180 top
PQ222  LP2305LT1G_SOT23-3  [NTR4502PT1G_SOT23-3]  64.11 35.01 90 top
PQ223  -  [DMN66D0LDW-7_SOT363-6]  58.27 33.23 90 top
PQ224  S TR 2N7002KW 1N SOT323-3  [SSM3K7002FU_SC70-3]  56.08 67.23 0 bottom
PQ302  -  [DMN65D8LW-7_SOT323-3]  39.03 22.56 270 top
PQ303  -  [SIR472DP-T1-GE3_POWERPAK8-5]  56.64 29.54 270 bottom
PQ304  -  [SI7716ADN-T1-GE3_POWERPAK8-5]  54.09 31.62 90 bottom
PQ305  -  [SI4835DDY-T1-E3_SO8]  74.28 33.22 0 bottom
PQ400  -  [DMN66D0LDW-7_SOT363-6]  166.79 58.27 270 top
PQ1302  -  [AON7934_DFN3X3A8-10]  70.32 62.02 180 bottom
PR100  100K_0402_5%  [R_0402]  66.02 18.88 270 top
PR101  0_0402_5%  [R_0402]  28.85 71.08 0 top
PR102  2.2K_0402_5%  [R_0402]  26.39 70.14 270 top
PR103  33_0402_5%  [R_0402]  26.39 67.45 90 top
PR104  100K_0402_1%  [R_0402]  28.93 72.02 90 top
PR105  10K_0402_1%  [R_0402]  33.17 71.46 0 top
PR106  15K_0402_1%  [R_0402]  29.82 72.93 270 top
PR107  4.7K_0805_5%  [R_0805]  29.21 76.51 270 top
PR200  0.01_1206_1%  [R_1206_4P-D]  55.09 58.04 90 bottom
PR201  100K_0402_5%  [R_0402]  54.51 54.7 0 top
PR202  1M_0402_1%  [R_0402]  55.14 54.06 0 bottom
PR203  1M_0402_1%  [R_0402]  29.44 76.74 270 bottom
PR204  100K_0402_5%  [R_0402]  18.59 72.98 180 top
PR205  100K_0402_5%  [R_0402]  35.74 78.95 180 bottom
PR206  100K_0402_5%  [R_0402]  21.23 76.29 0 top
PR207  100K_0402_5%  [R_0402]  56.29 54.7 0 top
PR208  1M_0402_1%  [R_0402]  33.12 76.29 270 top
PR209  200K_0402_1%  [R_0402]  31.27 73.87 0 top
PR210  100K_0402_5%  [R_0402]  59.78 46.38 0 top
PR211  100K_0402_5%  [R_0402]  17.68 72.09 0 top
PR212  100K_0402_5%  [R_0402]  20.22 70.06 0 top
PR213  0_0402_5%  [R_0402]  60.3 55.97 0 top
PR214  0_0402_5%  [R_0402]  60.81 60.78 90 bottom
PR215  100K_0402_5%  [R_0402]  22.15 77.3 180 top
PR216  0_0402_5%  [R_0402]  58.29 60.49 0 top
PR217  0_0402_5%  [R_0402]  21.18 74.96 270 top
PR218  0_0402_5%  [R_0402]  62.09 49.93 180 top
PR219  1M_0402_1%  [R_0402]  32.23 75.4 90 top
PR220  0_0402_5%  [R_0402]  22.07 74.96 270 top
PR221  0_0402_5%  [R_0402]  57.51 61.63 270 bottom
PR222  44.2_0402_1%  [R_0402]  56.62 59.78 90 bottom
PR223  0_0402_5%  [R_0402]  61.7 59.51 90 bottom
PR224  120K_0402_1%  [R_0402]  92.25 73.62 180 top
PR225  0_0402_5%  [R_0402]  57.51 58.76 90 bottom
PR226  221K_0402_1%~D  [R_0402]  87.4 75.52 0 top
PR227  1.8M_0402_1%  [R_0402]  91.34 75.52 0 top
PR228  0_0402_5%  [R_0402]  35.79 73.19 270 top
PR229  0_0402_5%  [R_0402]  59.86 49.35 90 top
PR230  100K_0402_1%  [R_0402]  91.34 72.73 0 top
PR231  0.01_1206_1%  [R_1206_4P-D]  43.12 77.81 180 bottom
PR232  1M_0402_1%  [R_0402]  50.52 75.22 270 bottom
PR233  100K_0402_5%  [R_0402]  54.13 64.47 0 top
PR234  1M_0402_1%  [R_0402]  50.39 77.73 90 bottom
PR235  100K_0402_5%  [R_0402]  49 69.22 90 top
PR236  0_0402_5%  [R_0402]  40.11 77.22 90 top
PR237  1M_0402_1%  [R_0402]  45.44 78.27 270 top
PR238  0_0402_5%  [R_0402]  41 77.22 90 top
PR239  0_0402_5%  [R_0402]  51.36 79.59 180 bottom
PR240  100K_0402_1%  [R_0402]  63.14 64.35 0 bottom
PR241  1M_0402_1%  [R_0402]  51.41 74.3 90 bottom
PR242  100K_0402_5%  [R_0402]  55.91 64.47 0 top
PR243  200K_0402_1%  [R_0402]  50.44 80.48 0 bottom
PR244  200K_0402_1%  [R_0402]  46.53 73.87 180 top
PR245  100K_0402_5%  [R_0402]  49 71 90 top
PR246  100K_0402_1%  [R_0402]  61.44 65.06 270 bottom
PR247  100K_0402_5%  [R_0402]  50.78 70.11 270 top
PR248  0_0402_5%  [R_0402]  54.84 68.36 270 top
PR249  0_0402_5%  [R_0402]  54.84 66.58 270 top
PR250  0_0402_5%  [R_0402]  54.71 69.86 90 top
PR251  0_0402_5%  [R_0402]  50.78 71.92 270 top
PR252  100K_0402_1%  [R_0402]  85.7 68.74 270 top
PR253  100K_0402_1%  [R_0402]  92.25 68.8 180 top
PR254  130K_0402_1%  [R_0402]  84 70.82 180 top
PR255  100K_0402_1%  [R_0402]  63.22 23.66 270 top
PR256  100K_0402_1%  [R_0402]  64.87 20.86 270 top
PR257  100K_0402_1%  [R_0402]  62.33 23.66 270 top
PR258  1.8M_0402_1%  [R_0402]  85.83 69.86 90 top
PR259  180K_0402_1%  [R_0402]  64.95 16.47 180 top
PR260  180K_0402_1%  [R_0402]  56.03 18.63 0 top
PR261  100K_0402_1%  [R_0402]  56.03 20.41 0 top
PR262  1.8M_0402_1%  [R_0402]  64.03 15.58 0 top
PR263  1.8M_0402_1%  [R_0402]  58.4 15.27 270 top
PR264  150K_0402_1%  [R_0402]  82.65 74.08 270 top
PR265  0_0402_5%  [R_0402]  86.59 68.74 270 top
PR266  140K_0402_1%  [R_0402]  64.95 13.8 180 top
PR267  130K_0402_1%  [R_0402]  59.28 14.36 90 top
PR268  100K_0402_1%  [R_0402]  83.54 73.16 90 top
PR269  200K_0402_1%  [R_0402]  84.38 72.22 180 top
PR270  16.5K_0402_1%  [R_0402]  64.03 14.69 0 top
PR271  200K_0402_1%  [R_0402]  64.03 17.36 0 top
PR272  16.5K_0402_1%  [R_0402]  57.51 15.27 270 top
PR273  200K_0402_1%  [R_0402]  56.95 17.48 180 top
PR274  0_0402_5%  [R_0402]  91.34 67.9 0 top
PR275  100K_0402_1%  [R_0402]  57.13 35.65 180 top
PR276  2K_0402_1%  [R_0402]  54.64 35.77 270 top
PR277  0_0402_5%  [R_0402]  59.3 33.04 90 top
PR278  100K_0402_1%  [R_0402]  60.19 34.82 90 top
PR279  0_0402_5%  [R_0402]  59.3 35.7 270 top
PR280  0_0402_5%  [R_0402]  57.23 55.58 0 top
PR281  0_0402_5%  [R_0402]  60.19 33.04 90 top
PR282  100K_0402_5%  [R_0402]  60.11 47.57 90 top
PR283  100K_0402_5%  [R_0402]  62.36 47.08 270 bottom
PR284  0_0402_5%  [R_0402]  60.07 61.38 270 top
PR285  0_0402_5%  [R_0402]  54.45 65.6 270 bottom
PR286  0_0402_5%  [R_0402]  57.77 61.46 0 top
PR287  0_0402_5%  [R_0402]  93.18 70.6 180 top
PR288  0_0402_5%  [R_0402]  91.39 69.69 90 top
PR289  100K_0402_1%  [R_0402]  62.69 57.24 180 top
PR290  100K_0402_1%  [R_0402]  55.22 58.86 180 top
PR291  10K_0402_1%  [R_0402]  54.45 66.44 90 bottom
PR300  0.01_1206_1%  [R_1206_4P-D]  49.27 30.28 270 bottom
PR301  100K_0402_5%  [R_0402]  35.92 23.02 270 top
PR303  0_0402_5%  [R0402_0OHM]  45.39 23.96 180 bottom
PR304  0_0402_5%  [R0402_0OHM]  45.39 24.85 180 bottom
PR305  4.02K_0402_1%  [R_0402]  42.29 24.27 90 bottom
PR306  10_1206_1%  [R_1206]  44.04 22.95 90 top
PR307  294K_0402_1%  [R_0402]  39.47 22.11 90 bottom
PR308  2.2_0603_5%  [R_0603]  45.95 29.8 0 bottom
PR309  0_0402_5%  [R0402_0OHM]  37.64 30.31 180 bottom
PR310  49.9K_0402_1%  [R_0402]  38.58 22.11 90 bottom
PR311  0_0402_5%  [R0402_0OHM]  37.64 31.71 180 bottom
PR312  100K_0402_1%  [R_0402]  41.25 24.27 90 bottom
PR313  0.01_1206_1%  [R_1206_4P-D]  72.98 33.27 180 bottom
PR314  0_0402_5%  [R0402_0OHM]  42.14 22.11 90 bottom
PR315  0_0402_5%  [R0402_0OHM]  38.46 24.27 90 bottom
PR316  100_0402_1%  [R_0402]  36.73 29.17 0 bottom
PR317  154K_0402_1%  [R_0402]  41.25 23.02 270 bottom
PR318  0_0402_5%  [R0402_0OHM]  40.36 24.27 90 top
PR319  0_0402_5%  [R0402_0OHM]  40.18 27.14 180 top
PR320  10K_0402_1%  [R_0402]  45.24 32.34 0 bottom
PR321  4.7_1206_5%  [R_1206]  56.87 35.47 180 bottom
PR322  20K_0402_1%  [R_0402]  39.27 28.03 0 top
PR323  4.02K_0402_1%  [R_0402]  41.63 33.22 90 bottom
PR324  10_0603_1%  [R_0603]  39.22 33.11 90 bottom
PR325  1K_0402_1%  [R_0402]  37.69 32.98 0 top
PR326  0_0402_5%  [R0402_0OHM]  37.69 32.09 0 top
PR327  121K_0402_1%  [R_0402]  38.58 33.87 180 top
PR400  1M_0402_1%  [R_0402]  164.69 63.38 90 bottom
PR401  1.91K_0402_1%  [R_0402]  167.44 57.24 180 bottom
PR402  232K_0402_1%  [R_0402]  167.95 64.47 180 top
PR403  10K_0402_1%  [R_0402]  169.14 60.23 270 top
PR404  10K_0402_1%  [R_0402]  170.03 60.23 270 top
PR405  100_0402_1%  [R_0402]  166.52 58.12 0 bottom
PR406  76.8K_0402_1%  [R_0402]  167.03 63.59 0 top
PR407  22.1K_0402_1%  [R_0402]  174.14 55.71 0 top
PR408  1M_0402_1%  [R_0402]  167.95 62.7 180 top
PR409  232K_0402_1%  [R_0402]  167.95 61.81 180 top
PR410  48.7K_0402_1%  [R_0402]  166.6 59.06 90 bottom
PR411  10K_0402_1%  [R_0402]  163.81 60.79 270 bottom
PR412  76.8K_0402_1%  [R_0402]  167.03 60.92 0 top
PR413  42.2K_0402_1%  [R_0402]  165.71 59.98 270 bottom
PR500  0_0603_5%  [R0603_0OHM]  88.81 22.44 180 top
PR501  4.7_1206_5%  [R_1206]  84.68 21.1 90 top
PR502  100K_0402_5%  [R_0402]  88.37 17.94 270 bottom
PR503  0_0402_5%  [R0402_0OHM]  91.03 17.03 90 bottom
PR504  1K_0402_5%  [R_0402]  89.26 17.03 90 bottom
PR505  0_0603_5%  [R0603_0OHM]  62.4 44.03 180 top
PR506  0_0402_5%  [R_0402]  67.16 38.36 90 bottom
PR507  4.7_1206_5%  [R_1206]  59.28 42.5 270 top
PR508  499K_0402_1%  [R_0402]  66.27 38.36 90 bottom
PR509  499K_0402_1%  [R_0402]  65.38 39.28 270 bottom
PR510  0_0402_5%  [R0402_0OHM]  64.49 38.36 90 bottom
PR511  1K_0402_5%  [R_0402]  62.71 38.36 90 bottom
PR512  0_0805_5%  [R0805_0OHM]  70.28 42.67 90 top
PR513  0_0805_5%  [R0805_0OHM]  70.28 42.67 90 bottom
PR600  100K_0402_5%  [R_0402]  175.29 35.26 0 top
PR601  100K_0402_5%  [R_0402]  175.29 34.38 0 top
PR602  4.7_0603_5%  [R_0603]  172.95 26.06 270 top
PR603  100K_0402_1%  [R_0402]  173.41 31.58 180 top
PR604  0_0402_5%  [R_0402]  173.41 34.25 180 top
PR605  100K_0402_1%  [R_0402]  172.49 32.47 0 top
PR606  0_0402_5%  [R0402_0OHM]  172.49 33.36 0 top
PR607  0_0402_5%  [R0402_0OHM]  166.73 33.87 270 top
PR608  1M_0402_1%  [R_0402]  165.84 32.98 90 top
PR609  0_0402_5%  [R0402_0OHM]  163.04 31.2 0 top
PR610  1M_0402_1%  [R_0402]  163.93 30.31 180 top
PR611  0_0402_5%  [R_0402]  163.04 32.09 0 top
PR700  75K_0402_1%  [R_0402]  203.1 59.65 0 bottom
PR701  1M_0402_1%  [R_0402]  203.1 60.54 0 bottom
PR702  4.7_0603_5%  [R_0603]  202.03 60.92 270 bottom
PR703  0_0603_5%  [R0603_0OHM]  199.49 63.9 270 top
PR704  24.9K_0402_1%  [R_0402]  204.01 63.2 180 bottom
PR705  10K_0402_5%  [R_0402]  204.01 62.32 180 bottom
PR707  35.7K_0402_1%  [R_0402]  204.06 65.79 90 bottom
PR708  0_0402_5%  [R_0402]  204.01 63.2 180 top
PR709  0_0402_5%  [R0402_0OHM]  203.1 62.32 0 top
PR800  0_0402_5%  [R_0402]  173.08 78.95 270 top
PR801  0_0402_5%  [R0402_0OHM]  172.19 78.95 270 top
PR802  412K_0402_1%  [R_0402]  171.55 70.82 90 top
PR803  4.7_0603_5%  [R_0603]  170.03 77.43 90 top
PR804  324K_0402_1%  [R_0402]  172.44 71.71 270 top
PR805  100K_0402_5%  [R_0402]  169.77 70.8 90 top
PR806  0_0402_5%  [R0402_0OHM]  173.33 71.71 270 top
PR900  0_0402_5%  [R0402_0OHM]  173.2 43.39 180 top
PR901  0_0402_5%  [R_0402]  173.2 44.28 180 top
PR902  412K_0402_1%  [R_0402]  167.62 38.19 90 top
PR903  4.7_0805_5%  [R_0805]  165.29 41.87 180 top
PR904  324K_0402_1%  [R_0402]  165.79 38.95 180 top
PR905  100K_0402_5%  [R_0402]  165.41 40.47 180 top
PR906  0_0402_5%  [R0402_0OHM]  169.01 39.02 270 top
PR1024  0_0402_5%  [R0402_0OHM]  61.44 53.81 0 top
PR1025  0_0402_5%  [R0402_0OHM]  61.44 54.7 0 top
PR1027  0_0402_5%  [R0402_0OHM]  63.6 51.01 0 top
PR1028  10_0402_1%  [R_0402]  63.6 54.7 0 top
PR1029  0_0402_5%  [R0402_0OHM]  63.6 50.12 0 top
PR1058  11K_0402_1%  [R_0402]  65.76 58.17 90 bottom
PR1059  0_0402_5%  [R0402_0OHM]  63.3 65.24 180 top
PR1060  2K_0402_1%  [R_0402]  71.48 58.25 90 top
PR1061  475_0402_1%  [R_0402]  71.48 48.22 90 bottom
PR1062  11K_0402_1%  [R_0402]  70.59 46.82 0 bottom
PR1063  75_0402_1%  [R_0402]  64.49 53.81 180 bottom
PR1064  10K_0402_1%  [R_0402]  74.78 52.28 180 top
PR1065  2K_0402_1%  [R_0402]  67.79 46.06 90 top
PR1066  0_0402_5%  [R0402_0OHM]  63.48 55.58 90 bottom
PR1067  27.4K_0402_1%  [R_0402]  65 46.06 90 top
PR1068  1K_0402_1%  [R_0402]  74.91 57.62 0 top
PR1069  84.5K_0402_1%  [R_0402]  70.46 56.22 270 bottom
PR1070  49.9_0402_1%  [R_0402]  63.6 52.92 0 top
PR1071  80.6K_0402_1%  [R_0402]  70.97 51.39 0 bottom
PR1072  10K_0402_1%  [R_0402]  65.13 48.09 90 top
PR1073  316_0402_1%  [R_0402]  70.59 58.25 90 top
PR1074  100_0402_1%  [R_0402]  64.49 54.7 180 bottom
PR1075  1.33K_0402_1%  [R_0402]  66.65 58.17 90 top
PR1076  0_0402_5%  [R0402_0OHM]  63.6 53.81 0 top
PR1077  1.69K_0402_1%  [R_0402]  69.57 58.25 180 top
PR1078  11K_0402_1%  [R_0402]  73.64 55.13 0 bottom
PR1079  1.37K_0402_1%  [R_0402]  73.89 54.06 270 top
PR1080  0_0402_5%  [R0402_0OHM]  66.02 55.33 90 bottom
PR1081  316_0402_1%  [R_0402]  75.79 53.17 180 top
PR1082  2.2_0603_5%  [R_0603]  61.57 62.82 90 top
PR1083  0_0402_5%  [R0402_0OHM]  64.24 48.09 90 top
PR1084  45.3_0402_1%  [R_0402]  64.49 52.92 180 bottom
PR1085  348_0402_1%  [R_0402]  74.91 56.73 0 top
PR1086  4.7_1206_5%  [R_1206]  73.25 67.4 180 bottom
PR1087  1K_0402_1%  [R_0402]  72.37 48.22 90 bottom
PR1088  2.61K_0402_1%  [R_0402]  69.57 46.95 270 bottom
PR1089  2.61K_0402_1%  [R_0402]  64.87 58.17 90 bottom
PR1090  7.32K_0402_1%  [R_0402]  67.79 56.22 180 bottom
PR1091  3.65K_0603_1%  [R_0603]  65.7 60.16 180 bottom
PR1092  1K_0402_1%  [R_0402]  67.54 60.03 180 top
PR1093  2.49K_0402_1%  [R_0402]  68.68 48.22 180 top
PR1094  100K_0402_1%  [R_0402]  64.49 55.58 180 top
PR1095  1.91K_0402_1%  [R_0402]  63.6 51.9 0 top
PR1096  2K_0402_1%  [R_0402]  76.18 52.28 0 top
PR1097  4.42K_0402_1%  [R_0402]  73.76 54.24 0 bottom
PR1098  1K_0402_1%  [R_0402]  68.81 45.93 90 top
PR1099  86.6K_0402_1%  [R_0402]  66.78 51.65 270 bottom
PR1100  2.2_0603_5%  [R_0603]  84.62 66.63 180 top
PR1101  10_1206_1%  [R_1206]  86.97 63.71 270 top
PR1102  3.65K_0603_1%  [R_0603]  75.03 57.97 180 bottom
PR1103  0_0402_5%  [R0402_0OHM]  84.05 67.01 90 bottom
PR1104  5.11K_0402_1%  [R_0402]  79.22 67.01 90 bottom
PR1105  2.2_0603_5%  [R_0603]  77.64 56.35 0 top
PR1106  10_1206_1%  [R_1206]  86.84 56.41 270 top
PR1107  10_0402_1%  [R_0402]  76.24 48.1 270 bottom
PR1108  5.11K_0402_1%  [R_0402]  78.92 58.76 180 top
PR1109  100K_0402_1%  [R_0402]  74.59 49.03 90 bottom
PR1110  0_0402_5%  [R_0402]  85.5 59.27 0 bottom
PR1111  3.65K_0603_1%  [R_0603]  75.67 50.5 270 bottom
PR1112  100K_0402_1%  [R_0402]  73.7 49.03 90 bottom
PR1113  2.2_0603_5%  [R_0603]  77.38 48.85 0 top
PR1114  10_1206_1%  [R_1206]  86.97 48.79 270 top
PR1115  10_0402_1%  [R_0402]  74.52 46.9 270 bottom
PR1116  3.65K_0603_1%  [R_0603]  73.44 47.96 0 bottom
PR1117  5.11K_0402_1%  [R_0402]  80.42 50.76 0 bottom
PR1118  100K_0402_1%  [R_0402]  73.64 46.9 270 bottom
PR1119  0_0402_5%  [R0402_0OHM]  85.5 51.65 0 bottom
PR1120  100K_0402_1%  [R_0402]  73.62 45.11 0 bottom
PR1121  48.7K_0402_1%  [R_0402]  64.49 56.6 180 top
PR1122  3.92K_0402_1%  [R_0402]  66.02 48.09 90 top
PR1123  5.49K_0402_1%  [R_0402]  70.97 54.06 0 bottom
PR1124  100_0402_1%  [R_0402]  61.44 51.9 0 top
PR1125  0_0402_5%  [R0402_0OHM]  61.44 52.92 0 top
PR1126  27.4K_0402_1%  [R_0402]  73.81 51.39 0 top
PR1127  0_0402_5%  [R_0402]  69.7 49.11 270 top
PR1128  0_0402_5%  [R_0402]  73.76 50.5 0 top
PR1130  0_0402_5%  [R0402_0OHM-NPM]  88.29 62.95 0 bottom
PR1131  0_0402_5%  [R0402_0OHM-NPM]  92.51 62.95 180 bottom
PR1132  0_0402_5%  [R0402_0OHM-NPM]  88.29 54.95 0 bottom
PR1133  0_0402_5%  [R0402_0OHM-NPM]  92.43 54.95 180 bottom
PR1134  0_0402_5%  [R0402_0OHM-NPM]  88.29 47.33 0 bottom
PR1135  0_0402_5%  [R0402_0OHM-NPM]  92.38 47.33 180 bottom
PR1136  0_0402_5%  [R0402_0OHM-NPM]  73.62 62.38 0 bottom
PR1137  0_0402_5%  [R0402_0OHM-NPM]  76.7 62.38 180 bottom
PR1400  0_0402_5%  [R_0402]  172.95 54.39 270 top
PR1401  0_0402_5%  [R0402_0OHM]  176.51 54.26 270 top
PR1402  0_0402_5%  [R_0402]  175.62 53.35 90 top
PR1403  4.7_0603_5%  [R_0603]  170.35 47.2 180 top
PR1404  10K_0402_1%  [R_0402]  176.63 45.81 90 top
PR1405  10K_0402_1%  [R_0402]  178.54 47.84 90 top
PR1406  10K_0402_1%  [R_0402]  175.74 46.69 270 top
PR1407  10K_0402_1%  [R_0402]  177.65 48.73 270 top
PR1408  100_0402_1%  [R_0402]  171.3 45.81 90 top
PR1409  0_0402_5%  [R0402_0OHM]  172.19 46.69 270 top
PR1410  0_0402_5%  [R0402_0OHM]  173.08 46.69 270 top
PR1411  0_0402_5%  [R_0402]  196.19 78.52 270 top
PR1412  130K_0402_1%  [R_0402]  199.11 75.7 90 bottom
PR1413  0_0402_5%  [R_0402]  200 76.62 270 bottom
PR1414  10K_0402_1%  [R_0402]  204.06 69.43 90 top
PR1415  10K_0402_1%  [R_0402]  203.89 72.98 180 top
PR1416  4.7_0603_5%  [R_0603]  195.17 71.97 0 top
PR1417  10K_0402_1%  [R_0402]  202.79 71.21 0 top
PR1418  10K_0402_1%  [R_0402]  202.97 73.87 0 top
PR1419  0_0402_5%  [R_0402]  203.89 72.09 180 top
PR1420  0_0402_5%  [R_0402]  203.18 69.43 90 top
PR1421  0_0402_5%  [R0402_0OHM]  198.48 72.78 90 bottom
PR1422  100K_0402_1%  [R_0402]  199.37 72.78 90 bottom
PR1423  10K_0402_1%  [R_0402]  173.84 54.39 270 top
PR1424  10K_0402_1%  [R_0402]  197.08 78.52 270 top
PR1425  100_0402_1%  [R_0402]  173.97 46.69 270 top
PR1500  0_0402_5%  [R_0402]  90.4 42.83 270 top
PR1501  0_0402_5%  [R0402_0OHM]  87.66 43.65 0 top
PR1502  0_0402_5%  [R_0402]  88.57 42.76 180 top
PR1503  10K_0402_1%  [R_0402]  86.84 34.93 90 top
PR1504  10K_0402_1%  [R_0402]  86.84 34.93 90 bottom
PR1505  4.7_0603_5%  [R_0603]  92.3 37.23 0 bottom
PR1506  100_0402_1%  [R_0402]  89.51 34.93 90 top
PR1507  10K_0402_1%  [R_0402]  85.95 35.85 270 top
PR1508  10K_0402_1%  [R_0402]  85.95 35.85 270 bottom
PR1509  0_0402_5%  [R0402_0OHM]  89.51 35.85 270 bottom
PR1510  0_0402_5%  [R0402_0OHM]  88.62 35.85 270 top
PR1511  0_0402_5%  [R_0402]  86.09 33.73 270 top
PR1512  0_0402_5%  [R0402_0OHM]  83.38 34.79 0 top
PR1513  0_0402_5%  [R_0402]  84.29 33.91 180 top
PR1514  10K_0402_1%  [R_0402]  82.78 25.54 90 bottom
PR1515  10K_0402_1%  [R_0402]  81.81 28.66 0 bottom
PR1516  4.7_0603_5%  [R_0603]  89.89 27.26 270 bottom
PR1517  10K_0402_1%  [R_0402]  83.67 26.45 270 bottom
PR1518  10K_0402_1%  [R_0402]  82.73 27.77 180 bottom
PR1519  100_0402_1%  [R_0402]  88.11 25.54 90 bottom
PR1520  0_0402_5%  [R0402_0OHM]  87.22 26.45 270 bottom
PR1521  0_0402_5%  [R0402_0OHM]  86.34 26.45 270 bottom
PR1522  10K_0402_1%  [R_0402]  89.51 42.83 270 top
PR1523  10K_0402_1%  [R_0402]  85.2 33.73 270 top
PR1524  0_0402_5%  [R0402_0OHM]  81.89 26.45 270 bottom
PR1525  100K_0402_1%  [R_0402]  81 26.45 270 bottom
PR1526  100_0402_1%  [R_0402]  88.62 35.85 270 bottom
PR1527  100_0402_1%  [R_0402]  85.45 26.45 270 bottom
PR1528  0_0805_5%  [R_0805]  95.56 40.69 270 bottom
PR1529  0_0805_5%  [R_0805]  91.99 32.74 90 bottom
PRP100  100_0804_8P4R_5%  [RP_0804_8P4R]  67.16 17.87 90 top
PU200  -  [INA199A1DCKR_SC70-6]  59.81 59.01 180 bottom
PU201  -  [LM393DMR2G_MICRO8]  89.85 72.01 90 top
PU202  -  [RT9069-33GB_SOT23-5]  65.41 67.45 270 bottom
PU203  -  [LM393DMR2G_MICRO8]  58.18 18.46 270 top
PU300  -  [BQ24777RUYR_WQFN28_4X4]  42.9 27.26 90 bottom
PU400  -  [LM393DMR2G_MICRO8]  163.85 59.94 0 top
PU401  -  [M74VHC1GT00DFT2G_SC70-5]  169.71 58.27 270 top
PU402  -  [M74VHC1GT00DFT2G_SC70-5]  172.51 58.27 270 top
PU500  -  [SY8286BRAC_QFN20_3X3]  88.88 22.31 270 bottom
PU501  SY8288CRAC_QFN20_3X3  [SY8286CRAC_QFN20_3X3]  62.59 44.03 270 bottom
PU600  -  [SY8210AQVC_QFN19_4X3]  168 32.6 270 top
PU700  -  [SYX196DQNC_QFN10_3X3]  201.1 62.33 90 bottom
PU800  -  [TLV62150RGTR_QFN16_3X3]  171.68 75.78 270 top
PU900  -  [TLV62150RGTR_QFN16_3X3]  166.98 42.88 270 top
PU1000  ISL95859HRTZ-T_TQFN40_5X5  [ISL95857HRTZ-T_TQFN40_5X5]  67.16 51.01 90 top
PU1100  -  [CSD97374CQ4M_SON8_3P5X4P5]  84.28 65.57 270 bottom
PU1101  -  [CSD97374CQ4M_SON8_3P5X4P5]  84.23 57.1 270 bottom
PU1102  -  [CSD97374CQ4M_SON8_3P5X4P5]  84.23 49.48 270 bottom
PU1305  -  [ISL95808HRZ-TS2378_DFN8_2X2]  62.97 61.68 0 top
PU1400  -  [TPS62134ARGT_QFN16_3X3]  172.92 50.62 0 top
PU1401  TPS62134DRGT_QFN16_3X3  [TPS62134BRGT_QFN16_3X3]  198.48 75.4 0 top
PU1500  -  [TPS62134CRGT_QFN16_3X3]  90.86 39.66 180 bottom
PU1501  -  [TPS62134CRGT_QFN16_3X3]  87.7 30.61 180 bottom
Q40  -  [L2N7002WT1G_SC-70-3]  183.57 18.62 180 top
Q41  -  [L2N7002WT1G_SC-70-3]  7.28 5.95 90 top
Q70  SI3457BDV-T1-E3_TSOP6~D  [SI3457BDV-T1-E3_TSOP6]  198.41 18.99 270 top
Q71  -  [L2N7002WT1G_SC-70-3]  203.37 17.74 90 top
Q72  -  [DMG2301U-7_SOT23-3]  198.16 46.06 90 top
QA1  -  [DMN66D0LDW-7_SOT363-6]  16.72 25.68 0 top
QA3  -  [DMN66D0LDW-7_SOT363-6]  16.37 32.09 180 top
QA6  DII-DMN65D8LW-7~D  [SSM3K7002FU_SC70-3]  19.03 31.52 180 top
QA9  DII-DMN65D8LW-7~D  [SSM3K7002FU_SC70-3]  19.28 24.53 180 top
QC2  -  [DMN66D0LDW-7_SOT363-6]  158.22 63.33 0 top
QE3  METR3904W-G_SC70-3  [MMBT3904WT1G_SC70-3]  135.99 61.81 270 top
QE4  METR3904W-G_SC70-3  [MMBT3904WT1G_SC70-3]  109.58 45.55 270 bottom
QE8  METR3904W-G_SC70-3  [MMBT3904WT1G_SC70-3]  193.9 79.97 180 top
QE9  -  [MMST3904-7-F_SOT323-3]  175.11 68.99 0 top
QE10  METR3904W-G_SC70-3  [MMBT3904WT1G_SC70-3]  148.95 36.66 0 top
QE11  METR3904W-G_SC70-3  [MMBT3904WT1G_SC70-3]  26.33 56.92 270 bottom
QE12  -  [DMN66D0LDW-7_SOT363-6]  187.55 74.76 270 top
QE13  -  [DMN66D0LDW-7_SOT363-6]  158.58 37.24 0 top
QE14  -  [DMN66D0LDW-7_SOT363-6]  34.18 35.23 270 top
QH7  -  [DMN66D0LDW-7_SOT363-6]  189.71 15.07 0 top
QH8  -  [DMN66D0LDW-7_SOT363-6]  9.05 7.75 90 top
QH9  -  [DMN66D0LDW-7_SOT363-6]  9.05 10.17 90 top
QT19  -  [L2N7002WT1G_SC-70-3]  31.09 60.85 0 top
QZ9  -  [DMG2301U-7_SOT23-3]  57.12 73.09 270 top
R7  1K_0402_1%  [R_0402]  27.18 37.17 90 top
R9  10_0201_1%  [R_0201]  141.07 57.43 270 top
R10  10_0201_1%  [R_0201]  159 61.07 270 top
R60  10K_0201_5%  [R_0201]  186.41 49.62 90 top
R78  200K_0402_1%  [R_0402]  159.04 40.99 270 top
R79  80.6_0402_1%~D  [R_0402]  160.71 36.09 180 top
R80  80.6_0402_1%~D  [R_0402]  32.79 34.83 270 top
R81  200K_0402_1%  [R_0402]  37.06 35.12 90 top
R93  0_0402_5%~D  [R_0402]  15.25 59.54 180 top
R94  0_0402_5%~D  [R_0402]  15.25 58.52 180 top
R95  0_0402_5%~D  [R_0402]  12.5 60.98 180 bottom
R96  0_0402_5%~D  [R_0402]  12.5 59.97 180 bottom
R104  0_0402_1%  [R0402_0OHM]  41.89 52.54 90 top
R220  10K_0402_5%~D  [R_0402]  185.65 40.6 270 bottom
R249  0_0402_5%~D  [R_0402]  188.98 63.41 270 bottom
R250  0_0402_1%  [R0402_0OHM]  188.06 63.33 180 bottom
R251  0_0402_1%  [R0402_0OHM]  191.44 62.95 180 top
R252  0_0402_5%~D  [R_0402]  173.2 67.52 0 top
R287  2.2K_0402_5%  [R_0402]  188.49 28.79 0 bottom
R288  2.2K_0402_5%  [R_0402]  188.49 27.9 0 bottom
R289  0_0402_1%  [R0402_0OHM]  203.1 31.96 270 top
R290  100K_0402_5%~D  [R_0402]  54.66 19.26 180 top
R291  0_0402_5%~D  [R_0402]  198.78 27.9 0 top
R292  0_0402_5%~D  [R_0402]  198.78 26.5 0 top
R531  0_0603_5%~D  [R_0603]  196.06 17.8 90 top
R535  1M_0402_5%~D  [R_0402]  199.67 14.31 0 top
R536  100K_0402_5%~D  [R_0402]  201.52 15.27 270 top
R540  220K_0402_5%~D  [R_0402]  193.02 27.52 180 top
R545  220K_0402_5%~D  [R_0402]  193.02 29.42 180 top
R884  10K_0402_5%~D  [R_0402]  162.79 15.2 0 top
R886  10K_0402_5%~D  [R_0402]  163.68 17.23 180 top
R910  820_0402_5%~D  [R_0402]  6.2 5.93 180 top
R911  820_0402_5%~D  [R_0402]  6.2 9.48 180 top
R912  820_0402_5%~D  [R_0402]  6.2 8.59 180 top
R913  820_0402_5%~D  [R_0402]  6.2 7.71 180 top
R916  820_0402_5%~D  [R_0402]  6.2 6.82 180 top
R1006  0_0402_1%  [R0402_0OHM]  182.6 50.2 270 top
R1027  100K_0402_5%~D  [R_0402]  204.14 42.38 180 top
R1103  10K_0402_5%~D  [R_0402]  165.25 16.21 0 top
R1104  4.7K_0402_5%  [R_0402]  189.71 18.25 0 top
R1105  4.7K_0402_5%  [R_0402]  190.98 14.06 180 top
R1125  0_0603_5%  [R0603_0OHM]  30.71 40.79 270 top
R1140  100K_0402_5%~D  [R_0402]  53.75 20.15 0 top
R1141  100K_0402_5%~D  [R_0402]  53.75 21.04 0 top
R1161  220K_0402_5%~D  [R_0402]  206.48 18.55 90 top
R1162  100K_0402_5%~D  [R_0402]  61.06 76.46 90 top
